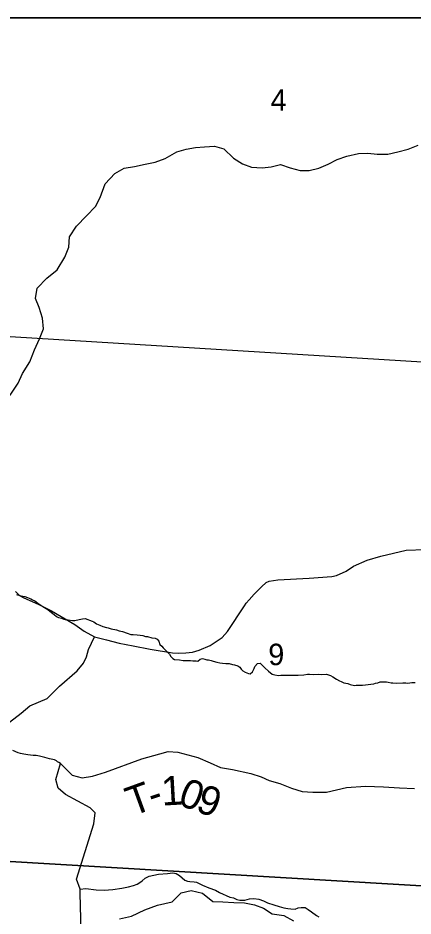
# Model space of a CAD drawing. Extents: x 0 to 45.4, y -2.2 to 22.
# Drawn here: x 5.221 to 5.991, y 19.147 to 20.9 of the extents above; entities that cross this region are included whole.
import ezdxf

# ---------------------------------------------------------------- set-up
doc = ezdxf.new("R2010")
doc.units = 0
for name, color, linetype in [('GM_X_Corporation', 7, 'Continuous'), ('GM_X_County_Road', 7, 'Continuous'), ('GM_X_Minor_River', 7, 'Continuous'), ('GM_X_Section_Text', 7, 'Continuous'), ('GM_X_State_Route', 7, 'Continuous'), ('GM_X_Township_Road', 7, 'Continuous'), ('GM_X_Township_Road_Text', 7, 'Continuous'), ('SH_Data', 7, 'Continuous')]:
    doc.layers.add(name, color=color, linetype=linetype)

msp = doc.modelspace()

# ---------------------------------------------------------------- linework, layer by layer
at = {"layer": 'GM_X_Corporation'}
for points in [[(8.9, 20.9), (2.1, 20.9), (2.1, 19.3454), (2.1562, 19.32), (2.2951, 19.2289), (2.4503, 19.1527), (2.5862, 19.0536)], [(6.2942, 20.9), (2.1, 20.9), (2.1, 19.3454), (2.1562, 19.32), (2.2951, 19.2289), (2.4503, 19.1527), (2.5862, 19.0536)]]:
    msp.add_lwpolyline(points, dxfattribs=at)
for points in [[(6.3012, 20.9), (5.1793, 20.9), (5.1309, 20.2827), (6.2516, 20.2138)], [(5.1309, 20.2827), (6.2516, 20.2138), (6.1827, 19.1954), (5.073, 19.2613)], [(6.1827, 19.1954), (6.1142, 18.166), (5.0121, 18.2353), (5.073, 19.2613)]]:
    msp.add_lwpolyline(points, close=True, dxfattribs=at)
at = {"layer": 'GM_X_County_Road'}
for points in [[(5.1961, 19.519), (5.2272, 19.543), (5.244, 19.5574), (5.2776, 19.5717), (5.3016, 19.5957), (5.3359, 19.6255), (5.3485, 19.6408), (5.3546, 19.653), (5.3586, 19.6675), (5.37, 19.6922)], [(5.3422, 19.1916), (5.342, 19.1995), (5.3352, 19.2192), (5.3688, 19.3272), (5.3712, 19.3487), (5.3616, 19.3583), (5.3136, 19.3847), (5.2992, 19.3967), (5.2944, 19.4135), (5.3038, 19.4447), (5.3004, 19.4467), (5.298, 19.4484), (5.2957, 19.4501), (5.2918, 19.4521), (5.2822, 19.4542), (5.2729, 19.4567), (5.2631, 19.4593), (5.2561, 19.4604), (5.2505, 19.4607), (5.2401, 19.4615), (5.2321, 19.4628), (5.226, 19.4644), (5.221, 19.466), (5.211, 19.4704)], [(5.3448, 19.0921), (5.3422, 19.1916)]]:
    msp.add_lwpolyline(points, dxfattribs=at)
at = {"layer": 'GM_X_Minor_River'}
for points in [[(5.1921, 20.1433), (5.2211, 20.1872), (5.2295, 20.2062), (5.244, 20.2289), (5.2532, 20.2524), (5.2631, 20.2736), (5.2708, 20.2934), (5.2686, 20.3139), (5.2619, 20.3351), (5.2551, 20.3526), (5.2582, 20.3723), (5.2773, 20.392), (5.297, 20.4086), (5.3123, 20.4329), (5.3199, 20.4526), (5.3215, 20.4731), (5.3352, 20.4935), (5.3543, 20.514), (5.3718, 20.5321), (5.3809, 20.5496), (5.3909, 20.5761), (5.4099, 20.5965), (5.4281, 20.6071), (5.4478, 20.6101), (5.4691, 20.6146), (5.488, 20.6183), (5.5077, 20.6258), (5.5305, 20.6387), (5.5487, 20.6439), (5.5669, 20.6469), (5.5843, 20.6483), (5.604, 20.6498), (5.6222, 20.6444), (5.641, 20.6261), (5.6584, 20.6155), (5.6758, 20.6086), (5.697, 20.6077), (5.7144, 20.6092), (5.7326, 20.6137), (5.7515, 20.6076), (5.7712, 20.6022), (5.7886, 20.6021), (5.8076, 20.6066), (5.8258, 20.6149), (5.8432, 20.624), (5.8622, 20.63), (5.8849, 20.6352), (5.9031, 20.6359), (5.9213, 20.6343), (5.9418, 20.6343), (5.9615, 20.6387), (5.9812, 20.644), (6.0009, 20.6515)], [(5.218, 19.775), (5.2266, 19.7722), (5.2304, 19.7717), (5.2342, 19.7709), (5.2391, 19.7689), (5.2458, 19.7665), (5.2492, 19.7646), (5.2537, 19.7626), (5.2593, 19.7576), (5.269, 19.751), (5.2724, 19.7494), (5.2788, 19.7455), (5.2863, 19.7397), (5.2911, 19.7354), (5.296, 19.7315), (5.2997, 19.73), (5.3054, 19.7283), (5.3103, 19.7267), (5.3156, 19.7255), (5.319, 19.7251), (5.3269, 19.7242), (5.3315, 19.7241), (5.3398, 19.7262), (5.3432, 19.7269), (5.3467, 19.7273), (5.352, 19.7276), (5.3655, 19.7228), (5.3689, 19.7212), (5.3741, 19.7177), (5.3802, 19.7149), (5.3862, 19.7126), (5.3933, 19.7102), (5.3967, 19.7094), (5.4024, 19.7074), (5.4129, 19.7057), (5.4178, 19.7041), (5.4246, 19.7028), (5.434, 19.6992), (5.4408, 19.6968), (5.4457, 19.6964), (5.4529, 19.6959), (5.459, 19.6954), (5.4643, 19.6946), (5.4692, 19.693), (5.4733, 19.6925), (5.482, 19.6901), (5.488, 19.6896), (5.4922, 19.6873), (5.4955, 19.6838), (5.4973, 19.6773), (5.501, 19.6738), (5.5036, 19.6704), (5.5073, 19.6673), (5.5159, 19.6584), (5.5185, 19.6538), (5.5226, 19.6499), (5.5259, 19.648), (5.5354, 19.647), (5.543, 19.6462), (5.5573, 19.6459), (5.5619, 19.6455), (5.5679, 19.645), (5.5713, 19.6445), (5.5763, 19.6486)], [(5.5763, 19.6486), (5.5805, 19.6501), (5.585, 19.6485), (5.5888, 19.6473), (5.5922, 19.6469), (5.5975, 19.646), (5.6016, 19.6448), (5.6084, 19.6424), (5.6141, 19.6412), (5.6194, 19.6407), (5.6258, 19.6402), (5.6326, 19.6401), (5.639, 19.6381), (5.6432, 19.6373), (5.6496, 19.6357), (5.6533, 19.6329), (5.6559, 19.6291), (5.6589, 19.6256), (5.6638, 19.6233), (5.6702, 19.6205), (5.6735, 19.6197), (5.6782, 19.6238), (5.6813, 19.6302), (5.6825, 19.6343), (5.6879, 19.64), (5.6932, 19.641), (5.7022, 19.6317), (5.7092, 19.6248), (5.7163, 19.6194), (5.7216, 19.6177), (5.7284, 19.6169), (5.7333, 19.6172), (5.7458, 19.617), (5.7515, 19.6176), (5.7591, 19.6171), (5.7671, 19.6174), (5.7784, 19.6179), (5.7853, 19.619), (5.7891, 19.6193), (5.7963, 19.6188), (5.8061, 19.619), (5.8129, 19.6185), (5.822, 19.6195), (5.8299, 19.6167), (5.8348, 19.6143), (5.8419, 19.6097), (5.8475, 19.6062), (5.8509, 19.605), (5.8558, 19.6026), (5.8637, 19.6009), (5.8686, 19.5993), (5.8766, 19.5973), (5.88, 19.5976), (5.8883, 19.5975), (5.8925, 19.5978), (5.8982, 19.5981), (5.9035, 19.5988), (5.9084, 19.5994), (5.9145, 19.6005), (5.9179, 19.6016), (5.9221, 19.6026), (5.9267, 19.6041), (5.9331, 19.6043), (5.9392, 19.6042), (5.9426, 19.6038), (5.9482, 19.6026), (5.9516, 19.6021), (5.9585, 19.602), (5.9713, 19.6026), (5.977, 19.6021), (5.9808, 19.602), (5.985, 19.6023), (5.9888, 19.6027), (5.9952, 19.6029)], [(5.4189, 19.142), (5.4424, 19.1472), (5.4682, 19.1593), (5.4925, 19.1683), (5.5213, 19.1751), (5.5388, 19.1925), (5.5585, 19.197), (5.5805, 19.1916), (5.6009, 19.1756), (5.6205, 19.1747), (5.6417, 19.1739), (5.6622, 19.1731), (5.6819, 19.1692), (5.6993, 19.1623), (5.7166, 19.1516), (5.7393, 19.1485), (5.7582, 19.1378)]]:
    msp.add_lwpolyline(points, dxfattribs=at)
at = {"layer": 'GM_X_State_Route'}
for points in [[(5.6715, 19.7643), (5.6812, 19.7757), (5.6953, 19.79), (5.7044, 19.798), (5.7105, 19.801), (5.7271, 19.8036), (5.7885, 19.8069), (5.8328, 19.8098), (5.8415, 19.8121), (5.8608, 19.82), (5.8749, 19.8298), (5.9014, 19.8419), (5.9279, 19.8498), (5.9778, 19.8613), (6.0143, 19.8628)], [(5.2162, 19.7805), (5.2241, 19.773), (5.2307, 19.7692), (5.2618, 19.755), (5.2864, 19.7427), (5.3319, 19.7162), (5.3496, 19.7034), (5.37, 19.6922), (5.3937, 19.6865), (5.4182, 19.6797), (5.4451, 19.6747), (5.4785, 19.6683), (5.5222, 19.6608), (5.5343, 19.6602), (5.5482, 19.6609), (5.5609, 19.6622), (5.574, 19.666), (5.5955, 19.6754), (5.6189, 19.6908), (5.6295, 19.7025), (5.6623, 19.7524), (5.6657, 19.7575), (5.6715, 19.7643)]]:
    msp.add_lwpolyline(points, dxfattribs=at)
at = {"layer": 'GM_X_Township_Road'}
for points in [[(5.3038, 19.4447), (5.3265, 19.4218), (5.3462, 19.4172), (5.3659, 19.4203), (5.3913, 19.4279), (5.4625, 19.4537), (5.4974, 19.4635), (5.5133, 19.4684), (5.5322, 19.4669), (5.5712, 19.4567), (5.5955, 19.446), (5.6159, 19.4373), (5.639, 19.4335), (5.6747, 19.4252), (5.6947, 19.4187), (5.7106, 19.4115), (5.7311, 19.4058), (5.7538, 19.3967), (5.775, 19.3902), (5.7959, 19.3887), (5.822, 19.3891), (5.8614, 19.3982), (5.8985, 19.4004), (5.9334, 19.3993), (5.9644, 19.3974), (5.9936, 19.3963)], [(5.342, 19.1995), (5.353, 19.2007), (5.3733, 19.1983), (5.3889, 19.1976), (5.4056, 19.1992), (5.4233, 19.2013), (5.4364, 19.2044), (5.4463, 19.207), (5.4534, 19.2096), (5.4583, 19.2124), (5.463, 19.2161), (5.4691, 19.2208), (5.4769, 19.2248), (5.4947, 19.2286), (5.5121, 19.2302), (5.5225, 19.2314), (5.5291, 19.23), (5.5354, 19.2262), (5.5408, 19.2215), (5.5462, 19.2173), (5.5512, 19.2152), (5.5556, 19.2145), (5.5641, 19.2142), (5.5686, 19.2133), (5.5805, 19.2072), (5.593, 19.2023), (5.6059, 19.1978), (5.6137, 19.1931), (5.6336, 19.1841), (5.6412, 19.1824), (5.6476, 19.1797), (5.6531, 19.178), (5.6632, 19.1782), (5.6722, 19.1806), (5.6807, 19.1811), (5.6901, 19.18), (5.6996, 19.1769), (5.7075, 19.173), (5.7197, 19.169), (5.73, 19.1657), (5.739, 19.1635), (5.7471, 19.1618), (5.7528, 19.1615), (5.7612, 19.1607), (5.7671, 19.1633), (5.7732, 19.1639), (5.7807, 19.1637), (5.7864, 19.16), (5.7932, 19.1556), (5.8029, 19.1482), (5.8075, 19.1458)]]:
    msp.add_lwpolyline(points, dxfattribs=at)
at = {"layer": 'SH_Data'}
msp.add_line((2.1, 20.9), (8.9, 20.9), dxfattribs=at)

# ---------------------------------------------------------------- texts
at = {"layer": 'GM_X_Section_Text'}
for s, p in [('4', (5.7133, 20.7188)), ('9', (5.7088, 19.6368))]:
    msp.add_text(s, height=0.0419, rotation=0, dxfattribs=at).set_placement(p)
at = {"layer": 'GM_X_Township_Road_Text'}
for s, rotation, p in [('T', 19.8984, (5.4438, 19.3416)), ('1', 3.2092, (5.5016, 19.3626)), ('0', 338.9561, (5.5303, 19.3655)), ('-', 18.3664, (5.4834, 19.356)), ('9', 340.7228, (5.5648, 19.3523))]:
    msp.add_text(s, height=0.0568, rotation=rotation, dxfattribs=at).set_placement(p)

doc.saveas('drawing.dxf')
